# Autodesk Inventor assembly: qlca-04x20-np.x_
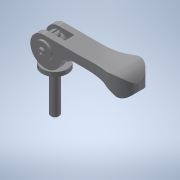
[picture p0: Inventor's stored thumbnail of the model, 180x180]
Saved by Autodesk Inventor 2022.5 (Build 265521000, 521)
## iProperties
Part Number: qlca-04x20-np.x_
Material: 一般
Document SubType Name: Assembly
Designer: ImaoCorp
Sending System: SOLIDWORKS 2017-2017317
MC: AMD64
MC_MODEL: Intel64 Family 6 Model 60 Stepping 3, GenuineIntel
OS: Windows_NT
FRU: Parasolid Version 29.0, build 201,  4-17-2017
FORMAT: text
GUISE: transmit
KEY: qlca-04x20-np
FILE: qlca-04x20-np.x_t
DATE: Wed Sep 04 15:48:56 2019
Author: ImaoCorp
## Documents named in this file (4)
- X:\14_SW2022-Inv2022\00_全2023-1023新製品(TCC)まで\q\qlca-04x20-np\QLCA-04X20-NP.iam
- X:\14_SW2022-Inv2022\00_全2023-1023新製品(TCC)まで\q\qlca-04x20-np\qlca-04x20-np_01.ipt
- X:\14_SW2022-Inv2022\00_全2023-1023新製品(TCC)まで\q\qlca-04x20-np\qlca-04x20-np_02.ipt
- X:\14_SW2022-Inv2022\00_全2023-1023新製品(TCC)まで\q\qlca-04x20-np\qlca-04x20-np_03.ipt
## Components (3 placed, 3 different names)
1. qlca-04x20-np_01
2. qlca-04x20-np_02
3. qlca-04x20-np_03
